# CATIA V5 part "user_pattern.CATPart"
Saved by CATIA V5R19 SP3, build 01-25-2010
Part number: Part32
Bounding box of the stored display mesh (mm): x -100 to 100, y -100 to 100, z 0 to 70
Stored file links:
  D:\Catia backup\user_pattern.CATPart

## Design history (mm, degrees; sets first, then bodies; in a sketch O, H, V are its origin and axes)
AxisSystem1: origin (0, 0, 0), X (1, 0, 0), Y (0, 1, 0), Z (0, 0, 1)
Body1 (main body)
  Sketch1 on XY plane of AxisSystem1, origin (0, 0, 0), H (1, 0, 0), V (0, 1, 0)
    line L1 (-100, 100) -> (100, 100)
    line L2 (100, 100) -> (100, -100)
    line L3 (100, -100) -> (-100, -100)
    line L4 (-100, -100) -> (-100, 100)
    horizontal: L1 H, L3 H
    vertical: L2 V, L4 V
  Pad1: profile Sketch1, direction (0, 0, 1), length 70
  Sketch2 on end face of Pad1, origin (66.0909, -77.8653, 70), H (1, 0, 0), V (0, 1, 0)
    point P1 (0, 0)
  Hole1: placed by Sketch2, at (66.0909, -77.8653, 70) direction (0, 0, -1), diameter 10, depth 10
  Sketch3 on end face of Pad1, origin (0, 0, 70), H (1, 0, 0), V (0, 1, 0)
    point P1 (-80, -40)
    point P2 (50, -30)
    point P3 (-50, 60)
    point P4 (50, 60)
    point P5 (-20, -10)
  UserPattern1: of Hole1, copies 6, at the points of Sketch3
